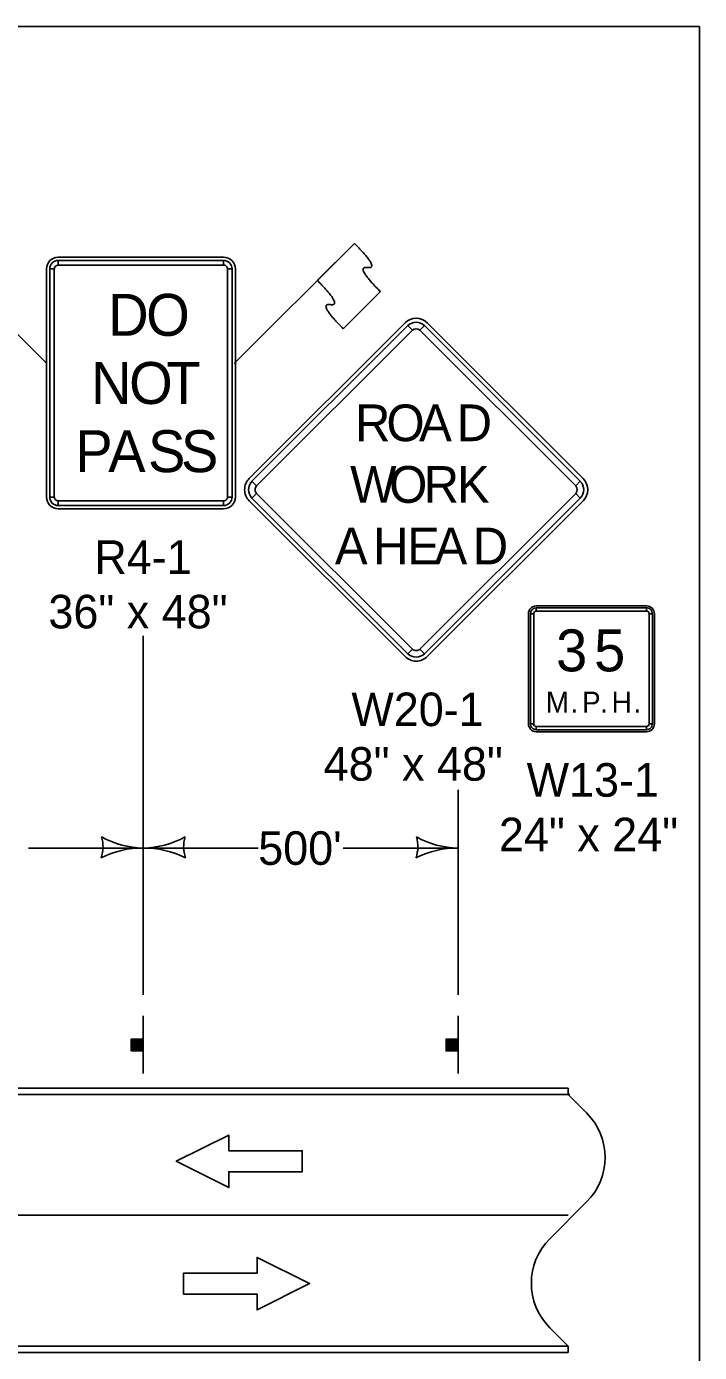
# Model space of a CAD drawing. Extents: x -2134934 to -2122394, y -2139046 to -2137036.
# Drawn here: x -2132120 to -2131799, y -2137668 to -2137036 of the extents above; entities that cross this region are included whole.
import ezdxf

# ---------------------------------------------------------------- set-up
doc = ezdxf.new("R2010")
doc.units = 0
for name, color, linetype in [('Barrier', 7, 'Continuous'), ('BridgeSuperStructureExisting', 7, 'Continuous'), ('Default', 7, 'Continuous'), ('DsnShtPlotIdentification', 7, 'Continuous'), ('TC_Barrier', 7, 'Continuous')]:
    doc.layers.add(name, color=color, linetype=linetype)

msp = doc.modelspace()

# ---------------------------------------------------------------- linework, layer by layer
at = {"layer": 'Barrier'}
for p, q in [((-2132110.46, -2137196.68), (-2132167.8, -2137139.38)), ((-2132021.17, -2137196.68), (-2131963.85, -2137139.36)), ((-2131963.85, -2137139.36), (-2131981.54, -2137157.04)), ((-2132026.22, -2137145.92), (-2132104.97, -2137145.92)), ((-2132104.97, -2137149.67), (-2132104.97, -2137147.48)), ((-2132026.22, -2137147.48), (-2132026.22, -2137149.67)), ((-2132110.6, -2137151.54), (-2132110.6, -2137260.29)), ((-2132109.04, -2137151.54), (-2132106.85, -2137151.54)), ((-2132024.35, -2137151.54), (-2132022.16, -2137151.54)), ((-2132020.6, -2137260.29), (-2132020.6, -2137151.54)), ((-2131969.15, -2137180.03), (-2131951.48, -2137162.35)), ((-2131939.75, -2137177.23), (-2132014, -2137251.47)), ((-2131938.42, -2137178.55), (-2131936.21, -2137180.76)), ((-2131932.68, -2137180.76), (-2131930.47, -2137178.55)), ((-2131854.9, -2137251.47), (-2131929.14, -2137177.23)), ((-2132010.46, -2137255.01), (-2132012.67, -2137252.8)), ((-2132012.67, -2137260.75), (-2132010.46, -2137258.54)), ((-2131856.22, -2137252.8), (-2131858.43, -2137255.01)), ((-2131858.43, -2137258.54), (-2131856.22, -2137260.75)), ((-2132106.85, -2137260.29), (-2132109.04, -2137260.29)), ((-2132104.97, -2137264.35), (-2132104.97, -2137262.17)), ((-2132026.22, -2137262.17), (-2132026.22, -2137264.35)), ((-2132022.16, -2137260.29), (-2132024.35, -2137260.29)), ((-2132014, -2137262.08), (-2131939.75, -2137336.33)), ((-2131929.14, -2137336.33), (-2131854.9, -2137262.08)), ((-2132104.97, -2137265.92), (-2132026.22, -2137265.92)), ((-2131824.68, -2137312.17), (-2131877.18, -2137312.17)), ((-2131877.18, -2137314.67), (-2131877.18, -2137313.1)), ((-2131824.68, -2137313.1), (-2131824.68, -2137314.67)), ((-2131880.93, -2137315.92), (-2131880.93, -2137368.42)), ((-2131879.99, -2137315.92), (-2131878.43, -2137315.92)), ((-2131823.43, -2137315.92), (-2131821.86, -2137315.92)), ((-2131820.93, -2137368.42), (-2131820.93, -2137315.92)), ((-2131936.21, -2137332.79), (-2131938.42, -2137335)), ((-2131930.47, -2137335), (-2131932.68, -2137332.79)), ((-2131878.43, -2137368.42), (-2131879.99, -2137368.42)), ((-2131877.18, -2137371.23), (-2131877.18, -2137369.67)), ((-2131877.18, -2137372.17), (-2131824.68, -2137372.17)), ((-2131824.68, -2137369.67), (-2131824.68, -2137371.23)), ((-2131821.86, -2137368.42), (-2131823.43, -2137368.42))]:
    msp.add_line(p, q, dxfattribs=at)
for points in [[(-2132026.22, -2137147.48), (-2132104.97, -2137147.48), (-2132104.97, -2137149.67), (-2132026.22, -2137149.67), (-2132026.22, -2137147.48)], [(-2132109.04, -2137151.54), (-2132109.04, -2137260.29), (-2132106.85, -2137260.29), (-2132106.85, -2137151.54), (-2132109.04, -2137151.54)], [(-2132022.16, -2137260.29), (-2132022.16, -2137151.54), (-2132024.35, -2137151.54), (-2132024.35, -2137260.29), (-2132022.16, -2137260.29)], [(-2131938.42, -2137178.55), (-2132012.67, -2137252.8), (-2132010.46, -2137255.01), (-2131936.21, -2137180.76), (-2131938.42, -2137178.55)], [(-2131856.22, -2137252.8), (-2131930.47, -2137178.55), (-2131932.68, -2137180.76), (-2131858.43, -2137255.01), (-2131856.22, -2137252.8)], [(-2132012.67, -2137260.75), (-2131938.42, -2137335), (-2131936.21, -2137332.79), (-2132010.46, -2137258.54), (-2132012.67, -2137260.75)], [(-2131930.47, -2137335), (-2131856.22, -2137260.75), (-2131858.43, -2137258.54), (-2131932.68, -2137332.79), (-2131930.47, -2137335)], [(-2132104.97, -2137264.35), (-2132026.22, -2137264.35), (-2132026.22, -2137262.17), (-2132104.97, -2137262.17), (-2132104.97, -2137264.35)], [(-2131824.68, -2137313.1), (-2131877.18, -2137313.1), (-2131877.18, -2137314.67), (-2131824.68, -2137314.67), (-2131824.68, -2137313.1)], [(-2131879.99, -2137315.92), (-2131879.99, -2137368.42), (-2131878.43, -2137368.42), (-2131878.43, -2137315.92), (-2131879.99, -2137315.92)], [(-2131821.86, -2137368.42), (-2131821.86, -2137315.92), (-2131823.43, -2137315.92), (-2131823.43, -2137368.42), (-2131821.86, -2137368.42)], [(-2131877.18, -2137371.23), (-2131824.68, -2137371.23), (-2131824.68, -2137369.67), (-2131877.18, -2137369.67), (-2131877.18, -2137371.23)]]:
    msp.add_lwpolyline(points, close=True, dxfattribs=at)
for centre, radius, start, end in [((-2132104.97, -2137151.54), 5.62, 90.00021, 179.99985), ((-2132104.97, -2137151.54), 4.06, 90.00021, 179.99985), ((-2132104.97, -2137151.54), 1.87, 90.00021, 179.99985), ((-2132026.22, -2137151.54), 5.62, 0, 90.00021), ((-2132026.22, -2137151.54), 4.06, 0, 90.00021), ((-2132026.22, -2137151.54), 1.87, 0, 90.00021), ((-2131934.45, -2137182.53), 7.5, 44.99999, 134.99974), ((-2131934.45, -2137182.53), 5.62, 44.99999, 134.99974), ((-2131934.45, -2137182.53), 2.5, 44.99999, 134.99974), ((-2132008.69, -2137256.78), 7.5, 134.99974, 224.99995), ((-2131860.2, -2137256.78), 7.5, 315.00016, 44.9998), ((-2132008.69, -2137256.78), 5.62, 134.99974, 224.99995), ((-2132008.69, -2137256.78), 2.5, 134.99974, 224.99995), ((-2131860.2, -2137256.78), 2.5, 315.00016, 44.9998), ((-2131860.2, -2137256.78), 5.62, 315.00016, 44.9998), ((-2132104.97, -2137260.29), 5.62, 179.99985, 270.00006), ((-2132104.97, -2137260.29), 4.06, 179.99985, 270.00006), ((-2132104.97, -2137260.29), 1.87, 179.99985, 270.00006), ((-2132026.22, -2137260.29), 5.62, 270.00006, 0.00027), ((-2132026.22, -2137260.29), 4.06, 270.00006, 0.00027), ((-2132026.22, -2137260.29), 1.87, 270.00006, 0.00027), ((-2131877.18, -2137315.92), 3.75, 90.00021, 179.99985), ((-2131877.18, -2137315.92), 2.81, 90.00021, 179.99985), ((-2131877.18, -2137315.92), 1.25, 90.00021, 179.99985), ((-2131824.68, -2137315.92), 3.75, 0, 90.00021), ((-2131824.68, -2137315.92), 2.81, 0, 90.00021), ((-2131824.68, -2137315.92), 1.25, 0, 90.00021), ((-2131934.45, -2137331.02), 2.5, 224.99995, 315.00016), ((-2131934.45, -2137331.02), 7.5, 224.99995, 315.00016), ((-2131934.45, -2137331.02), 5.62, 224.99995, 315.00016), ((-2131877.18, -2137368.42), 3.75, 179.99985, 270.00006), ((-2131877.18, -2137368.42), 2.81, 179.99985, 270.00006), ((-2131877.18, -2137368.42), 1.25, 179.99985, 270.00006), ((-2131824.68, -2137368.42), 3.75, 270.00006, 0.00027), ((-2131824.68, -2137368.42), 2.81, 270.00006, 0.00027), ((-2131824.68, -2137368.42), 1.25, 270.00006, 0.00027)]:
    msp.add_arc(centre, radius, start, end, dxfattribs=at)
for points in [[(-2131951.48, -2137162.35), (-2131963.85, -2137149.98), (-2131951.48, -2137151.75), (-2131963.85, -2137139.36)], [(-2131981.54, -2137157.04), (-2131969.16, -2137169.43), (-2131981.53, -2137167.66), (-2131969.15, -2137180.03)]]:
    msp.add_open_spline(points, degree=2, dxfattribs=at)
at = {"layer": 'BridgeSuperStructureExisting'}
for p, q in [((-2132064.45, -2137497.66), (-2132064.45, -2137326.42)), ((-2131914.45, -2137497.66), (-2131914.45, -2137399.97)), ((-2132119.2, -2137427.66), (-2132064.45, -2137427.66)), ((-2132064.45, -2137427.66), (-2132009.7, -2137427.66)), ((-2131969.2, -2137427.66), (-2131914.45, -2137427.66)), ((-2132064.45, -2137535.16), (-2132064.45, -2137507.66)), ((-2131914.45, -2137535.16), (-2131914.45, -2137507.66)), ((-2132069.77, -2137524.3), (-2132069.77, -2137518.71)), ((-2132069.45, -2137518.71), (-2132069.45, -2137524.3)), ((-2132069.23, -2137524.3), (-2132069.23, -2137518.71)), ((-2132068.91, -2137518.71), (-2132068.91, -2137524.3)), ((-2132068.69, -2137524.3), (-2132068.7, -2137518.71)), ((-2132068.27, -2137518.71), (-2132068.25, -2137524.3)), ((-2132068.05, -2137524.3), (-2132068.05, -2137518.71)), ((-2132067.62, -2137518.71), (-2132067.62, -2137524.3)), ((-2132067.24, -2137524.3), (-2132067.24, -2137518.71)), ((-2132066.92, -2137518.71), (-2132066.9, -2137524.3)), ((-2132066.7, -2137524.3), (-2132066.7, -2137518.71)), ((-2132066.43, -2137518.71), (-2132066.43, -2137524.3)), ((-2132066.1, -2137524.3), (-2132066.1, -2137518.71)), ((-2132065.89, -2137518.71), (-2132065.89, -2137524.3)), ((-2132065.67, -2137524.3), (-2132065.67, -2137518.71)), ((-2132065.4, -2137518.71), (-2132065.4, -2137524.3)), ((-2132065.14, -2137524.3), (-2132065.14, -2137518.71)), ((-2132064.86, -2137518.71), (-2132064.86, -2137524.3)), ((-2131919.77, -2137524.3), (-2131919.77, -2137518.71)), ((-2131919.45, -2137518.71), (-2131919.45, -2137524.3)), ((-2131919.23, -2137524.3), (-2131919.23, -2137518.71)), ((-2131918.91, -2137518.71), (-2131918.91, -2137524.3)), ((-2131918.69, -2137524.3), (-2131918.7, -2137518.71)), ((-2131918.27, -2137518.71), (-2131918.25, -2137524.3)), ((-2131918.05, -2137524.3), (-2131918.05, -2137518.71)), ((-2131917.62, -2137518.71), (-2131917.62, -2137524.3)), ((-2131917.24, -2137524.3), (-2131917.24, -2137518.71)), ((-2131916.92, -2137518.71), (-2131916.9, -2137524.3)), ((-2131916.7, -2137524.3), (-2131916.7, -2137518.71)), ((-2131916.43, -2137518.71), (-2131916.43, -2137524.3)), ((-2131916.1, -2137524.3), (-2131916.1, -2137518.71)), ((-2131915.89, -2137518.71), (-2131915.89, -2137524.3)), ((-2131915.67, -2137524.3), (-2131915.67, -2137518.71)), ((-2131915.4, -2137518.71), (-2131915.4, -2137524.3)), ((-2131915.14, -2137524.3), (-2131915.14, -2137518.71)), ((-2131914.86, -2137518.71), (-2131914.86, -2137524.3)), ((-2131861.99, -2137545.16), (-2133174.44, -2137545.16)), ((-2131853.21, -2137553.94), (-2131861.99, -2137545.16)), ((-2131853.2, -2137553.95), (-2131861.99, -2137545.16)), ((-2131870.78, -2137613.94), (-2131853.21, -2137596.37)), ((-2131870.78, -2137613.95), (-2131853.2, -2137596.37)), ((-2131861.99, -2137665.16), (-2131870.78, -2137656.37)), ((-2131861.99, -2137665.16), (-2131870.78, -2137656.37)), ((-2133364.44, -2137665.16), (-2131861.99, -2137665.16))]:
    msp.add_line(p, q, dxfattribs=at)
for points in [[(-2132064.54, -2137518.71), (-2132064.54, -2137524.34), (-2132070.17, -2137524.34), (-2132070.17, -2137518.71)], [(-2131914.54, -2137518.71), (-2131914.54, -2137524.34), (-2131920.17, -2137524.34), (-2131920.17, -2137518.71)], [(-2131988.74, -2137582), (-2131988.74, -2137572), (-2132023.74, -2137572), (-2132023.74, -2137564.5), (-2132048.74, -2137577), (-2132023.74, -2137589.5), (-2132023.74, -2137582)], [(-2132045.26, -2137630.33), (-2132045.26, -2137640.33), (-2132010.26, -2137640.33), (-2132010.26, -2137647.83), (-2131985.26, -2137635.33), (-2132010.26, -2137622.83), (-2132010.26, -2137630.33)]]:
    msp.add_lwpolyline(points, close=True, dxfattribs=at)
for points in [[(-2132023.74, -2137582), (-2132023.74, -2137589.5), (-2132048.74, -2137577), (-2132023.74, -2137564.5), (-2132023.74, -2137572), (-2131988.74, -2137572), (-2131988.74, -2137582), (-2132023.74, -2137582)], [(-2132010.26, -2137630.33), (-2132010.26, -2137622.83), (-2131985.26, -2137635.33), (-2132010.26, -2137647.83), (-2132010.26, -2137640.33), (-2132045.26, -2137640.33), (-2132045.26, -2137630.33), (-2132010.26, -2137630.33)]]:
    msp.add_lwpolyline(points, dxfattribs=at)
for centre, radius, start, end in [((-2132100.06, -2137427.04), 16.42, 341.26665, 16.73335), ((-2132063.69, -2137385.17), 42.5, 240.92751, 268.9824), ((-2132065.2, -2137385.17), 42.5, 271.0176, 299.07249), ((-2132028.83, -2137427.04), 16.42, 163.26665, 198.73335), ((-2131950.06, -2137427.04), 16.42, 341.26665, 16.73335), ((-2131913.69, -2137385.17), 42.5, 240.92751, 268.9824), ((-2132065.18, -2137470.15), 42.5, 89.0176, 117.07249), ((-2132063.72, -2137470.15), 42.5, 62.92751, 90.9824), ((-2131915.18, -2137470.15), 42.5, 89.0176, 117.07249), ((-2131874.42, -2137575.16), 30, 315, 45), ((-2131874.42, -2137575.16), 30, 315, 45), ((-2131849.56, -2137635.16), 30, 135, 225), ((-2131849.56, -2137635.16), 30, 135, 225)]:
    msp.add_arc(centre, radius, start, end, dxfattribs=at)
at = {"layer": 'Default'}
msp.add_lwpolyline([(-2134934.44, -2137035.95), (-2131799.45, -2137035.95), (-2131799.45, -2139045.94), (-2134934.44, -2139045.94)], close=True, dxfattribs=at)
at = {"layer": 'DsnShtPlotIdentification'}
for p, q in [((-2131861.99, -2137542.16), (-2132547.01, -2137542.16)), ((-2131861.99, -2137542.16), (-2131861.99, -2137545.16)), ((-2131861.99, -2137545.16), (-2131861.99, -2137542.16)), ((-2132509.45, -2137545.16), (-2131861.99, -2137545.16)), ((-2131861.95, -2137602.66), (-2132514.45, -2137602.66)), ((-2133364.44, -2137665.16), (-2131861.99, -2137665.16)), ((-2133364.44, -2137665.16), (-2131861.99, -2137665.16)), ((-2133364.44, -2137668.16), (-2131861.99, -2137668.16)), ((-2132442.06, -2137668.16), (-2131861.99, -2137668.16)), ((-2131861.99, -2137665.16), (-2132441.05, -2137665.16)), ((-2131861.99, -2137668.16), (-2131861.99, -2137665.16)), ((-2131861.99, -2137668.16), (-2131861.99, -2137665.16))]:
    msp.add_line(p, q, dxfattribs=at)
for points in [[(-2133174.44, -2137542.16), (-2131861.99, -2137542.16)], [(-2133174.44, -2137545.16), (-2131861.99, -2137545.16)], [(-2133173.75, -2137545.16), (-2131861.29, -2137545.16)]]:
    msp.add_lwpolyline(points, dxfattribs=at)
at = {"layer": 'TC_Barrier'}
msp.add_line((-2131951.48, -2137162.35), (-2131969.15, -2137180.03), dxfattribs=at)
for points in [[(-2131963.85, -2137139.36), (-2131951.48, -2137151.75), (-2131963.85, -2137149.98), (-2131951.48, -2137162.35)], [(-2131981.54, -2137157.04), (-2131969.16, -2137169.43), (-2131981.53, -2137167.66), (-2131969.15, -2137180.03)]]:
    msp.add_open_spline(points, degree=2, dxfattribs=at)

# ---------------------------------------------------------------- texts
at = {"layer": 'Barrier'}
for s, height, p in [('D', 20, (-2132081.22, -2137183.42)), ('O', 20, (-2132063.1, -2137183.42)), ('O', 20, (-2132071.22, -2137215.92)), ('N', 20, (-2132089.35, -2137215.92)), ('T', 20, (-2132053.41, -2137215.92)), ('R', 17.5, (-2131963.61, -2137233.65)), ('O', 17.5, (-2131948.6, -2137233.65)), ('A', 17.5, (-2131933.05, -2137233.65)), ('D', 17.5, (-2131915.17, -2137233.65)), ('P', 20, (-2132096.86, -2137248.42)), ('A', 20, (-2132081.18, -2137248.42)), ('S', 20, (-2132062.21, -2137248.42)), ('S', 20, (-2132046.52, -2137248.42)), ('W', 17.5, (-2131965.89, -2137263.03)), ('O', 17.5, (-2131947.3, -2137263.03)), ('R', 17.5, (-2131930.89, -2137263.03)), ('K', 17.5, (-2131915.03, -2137263.03)), ('A', 17.5, (-2131973.17, -2137292.4)), ('H', 17.5, (-2131954.96, -2137292.4)), ('E', 17.5, (-2131938.73, -2137292.4)), ('A', 17.5, (-2131925.69, -2137292.4)), ('D', 17.5, (-2131907.48, -2137292.4)), ('R4-1', 16, (-2132087.76, -2137296.92)), ('36" x 48"', 16, (-2132109.67, -2137322.92)), ('3', 20, (-2131867.78, -2137343.41)), ('5', 20, (-2131849.65, -2137343.41)), ('W20-1', 16, (-2131965.3, -2137369.52)), ('M', 10, (-2131872.7, -2137363.1)), ('P', 10, (-2131855.45, -2137363.1)), ('H', 10, (-2131841.33, -2137363.1)), ('.', 10, (-2131860.91, -2137363.1)), ('.', 10, (-2131846.79, -2137363.1)), ('.', 10, (-2131830.86, -2137363.1)), ('48" x 48"', 16, (-2131978.51, -2137395.52)), ('W13-1', 16, (-2131881.78, -2137403.17)), ('24" x 24"', 16, (-2131894.99, -2137429.17))]:
    msp.add_text(s, height=height, dxfattribs=at).set_placement(p)
at = {"layer": 'BridgeSuperStructureExisting'}
msp.add_text("500'", height=16, dxfattribs=at).set_placement((-2132009.7, -2137435.66))

doc.saveas('drawing.dxf')
